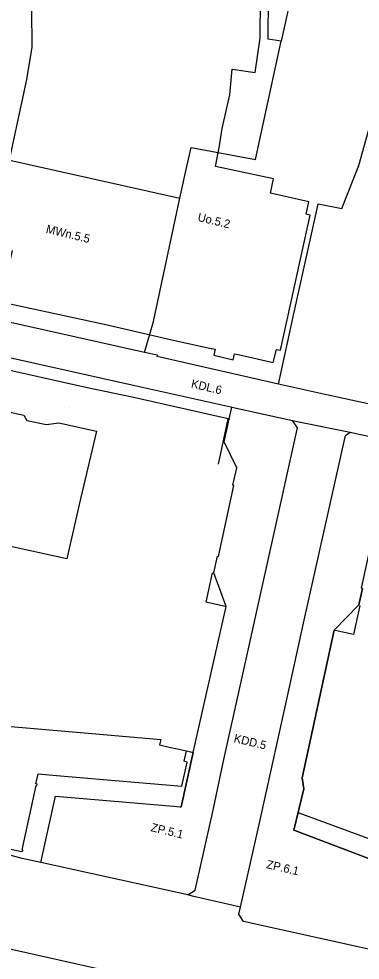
# Model space of a CAD drawing. Extents: x 7429686 to 7432896, y 5547954 to 5550600.
# Drawn here: x 7431167.9 to 7431331.5, y 5549633.8 to 5550085.1 of the extents above; entities that cross this region are included whole.
import ezdxf

# ---------------------------------------------------------------- set-up
doc = ezdxf.new("R2010")
doc.units = 0
for name, color, linetype in [('linie rozgraniczające', 7, 'Continuous'), ('obowiązująca linia zabudowy', 7, 'Continuous'), ('oznaczenia przeznaczeń', 7, 'Continuous')]:
    doc.layers.add(name, color=color, linetype=linetype)

msp = doc.modelspace()

# ---------------------------------------------------------------- linework, layer by layer
at = {"layer": 'linie rozgraniczające'}
for p, q in [((7431332.59, 5549812.04), (7431330.89, 5549804.16)), ((7431330.89, 5549804.16), (7431319.02, 5549792.1)), ((7431319.02, 5549792.1), (7431303.72, 5549721.28)), ((7431303.72, 5549721.28), (7431304.47, 5549715.98)), ((7431300.13, 5549695.97), (7431359.15, 5549673.6))]:
    msp.add_line(p, q, dxfattribs=at)
for points in [[(7431302.5, 5550115.02), (7431293.68, 5550074.41)], [(7431287.45, 5550075.33), (7431287.61, 5550096.06)], [(7431281.37, 5550017.75), (7431293.68, 5550074.41)], [(7431293.68, 5550074.41), (7431287.45, 5550075.33)], [(7431330.83, 5550014.86), (7431336.35, 5550034.33)], [(7431248.36, 5550014.31), (7431250.5, 5550023.42)], [(7431250.5, 5550023.42), (7431281.37, 5550017.75)], [(7431157.75, 5550018.66), (7431245.1, 5549999.15)], [(7431245.1, 5549999.15), (7431248.36, 5550014.31)], [(7431322.65, 5549994.25), (7431330.83, 5550014.86)], [(7431232.38, 5549940.01), (7431245.1, 5549999.15)], [(7431310.03, 5549990.54), (7431311.41, 5549996.45)], [(7431311.41, 5549996.45), (7431322.65, 5549994.25)], [(7431299.92, 5549944.45), (7431310.03, 5549990.54)], [(7431228.11, 5549925.18), (7431145.92, 5549943.57)], [(7431292.38, 5549910.01), (7431299.92, 5549944.45)], [(7431228.11, 5549925.18), (7431232.38, 5549940.01)], [(7431143.92, 5549927.01), (7431223.5, 5549909.33)], [(7431234.37, 5549923.82), (7431228.11, 5549925.18)], [(7431234.24, 5549923.16), (7431234.37, 5549923.82)], [(7431292.36, 5549910.01), (7431234.24, 5549923.16)], [(7431292.38, 5549910.01), (7431292.36, 5549910.01)], [(7431313.84, 5549905.24), (7431292.38, 5549910.01)], [(7431223.5, 5549909.33), (7431269.5, 5549899.12)], [(7431342.73, 5549898.88), (7431313.84, 5549905.24)], [(7431141.55, 5549901.35), (7431170.32, 5549895.1)], [(7431266.37, 5549882.27), (7431269.99, 5549899.01)], [(7431269.5, 5549899.12), (7431269.99, 5549899.01)], [(7431269.99, 5549899.01), (7431299.12, 5549892.54)], [(7431170.32, 5549895.1), (7431171.78, 5549892.56)], [(7431171.78, 5549892.56), (7431181.24, 5549890.55)], [(7431181.24, 5549890.55), (7431187.09, 5549891.39)], [(7431187.09, 5549891.39), (7431205.08, 5549887.43)], [(7431299.12, 5549892.54), (7431302.05, 5549891.89)], [(7431301.4, 5549888.96), (7431299.12, 5549892.54)], [(7431302.05, 5549891.89), (7431326.76, 5549886.99)], [(7431205.08, 5549887.43), (7431196.9, 5549852.2)], [(7431274.01, 5549765.16), (7431301.4, 5549888.96)], [(7431324.41, 5549885.42), (7431326.76, 5549886.99)], [(7431326.76, 5549886.99), (7431355.15, 5549880.69)], [(7431304.38, 5549795.32), (7431324.41, 5549885.42)], [(7431272.31, 5549869.87), (7431266.37, 5549882.27)], [(7431270.47, 5549861.47), (7431272.31, 5549869.87)], [(7431263.52, 5549827.4), (7431270.91, 5549861.34)], [(7431270.91, 5549861.34), (7431270.47, 5549861.47)], [(7431350.69, 5549635.72), (7431359.15, 5549673.6), (7431300.13, 5549695.97), (7431299.66, 5549696.15), (7431304.47, 5549715.98), (7431303.72, 5549721.28), (7431319.02, 5549792.1), (7431330.89, 5549804.16), (7431332.59, 5549812.04), (7431332.2, 5549812.2), (7431339.7, 5549846.45), (7431340.14, 5549846.42), (7431341.93, 5549854.71), (7431345.63, 5549857.59), (7431346.28, 5549858.1)], [(7431196.9, 5549852.2), (7431190.87, 5549826.26)], [(7431190.87, 5549826.26), (7431164.77, 5549831.94)], [(7431261.3, 5549819.53), (7431263.05, 5549827.55)], [(7431263.05, 5549827.55), (7431263.52, 5549827.4)], [(7431267.24, 5549803.35), (7431261.3, 5549819.53)], [(7431251.53, 5549733.37), (7431267.24, 5549803.35)], [(7431297.92, 5549766.13), (7431304.38, 5549795.32)], [(7431266.23, 5549729.93), (7431274.01, 5549765.16)], [(7431283.38, 5549700.36), (7431297.92, 5549766.13)], [(7431160.38, 5549746.12), (7431212.2, 5549741.68)], [(7431212.2, 5549741.68), (7431235.9, 5549739.65)], [(7431235.9, 5549739.65), (7431235.3, 5549737.02)], [(7431235.3, 5549737.02), (7431240.02, 5549735.96)], [(7431240.02, 5549735.96), (7431243.97, 5549735.1)], [(7431243.97, 5549735.1), (7431248.21, 5549734.1)], [(7431248.21, 5549734.1), (7431251.53, 5549733.37)], [(7431245.68, 5549707.34), (7431251.53, 5549733.37)], [(7431251.53, 5549733.37), (7431251.53, 5549733.37), (7431245.68, 5549707.34)], [(7431251.53, 5549733.37), (7431251.53, 5549733.37)], [(7431260.67, 5549704.33), (7431266.23, 5549729.93)], [(7431304.47, 5549715.98), (7431299.66, 5549696.15), (7431300.13, 5549695.97)], [(7431178.47, 5549680.56), (7431185.5, 5549712.42)], [(7431185.5, 5549712.42), (7431242.08, 5549707.64)], [(7431242.08, 5549707.64), (7431245.18, 5549707.38)], [(7431245.18, 5549707.38), (7431245.68, 5549707.34)], [(7431252.43, 5549667.33), (7431260.67, 5549704.33)], [(7431274.14, 5549659.27), (7431283.38, 5549700.36)], [(7431169.5, 5549682.54), (7431144.11, 5549689.49)], [(7431178.47, 5549680.56), (7431169.5, 5549682.54)], [(7431248.85, 5549665.05), (7431178.47, 5549680.56)], [(7431248.85, 5549665.05), (7431252.43, 5549667.33)], [(7431251.78, 5549664.4), (7431248.85, 5549665.05)], [(7431274.14, 5549659.27), (7431251.78, 5549664.4)], [(7431273.37, 5549655.85), (7431274.14, 5549659.27)], [(7431275.64, 5549652.27), (7431273.37, 5549655.85)], [(7431350.69, 5549635.72), (7431275.64, 5549652.27)], [(7431154.15, 5549641.32), (7431217.12, 5549627.23)]]:
    msp.add_lwpolyline(points, dxfattribs=at)
at = {"layer": 'obowiązująca linia zabudowy'}
for p, q in [((7431260.62, 5549926.99), (7431261.98, 5549926.69)), ((7431261.98, 5549926.69), (7431261.33, 5549923.82)), ((7431261.33, 5549923.82), (7431270.69, 5549921.69)), ((7431270.69, 5549921.69), (7431271.34, 5549924.52)), ((7431271.34, 5549924.52), (7431273.03, 5549924.13)), ((7431192.06, 5549898.79), (7431192.06, 5549898.79))]:
    msp.add_line(p, q, dxfattribs=at)
for points in [[(7431281.13, 5550059.4), (7431283.49, 5550075.92), (7431283.69, 5550095.26), (7431280.35, 5550111.61), (7431270.28, 5550128.36), (7431259.85, 5550141.49), (7431247.46, 5550147.97), (7431237.1, 5550160.93), (7431224.11, 5550167.3), (7431213.73, 5550180.15), (7431226.04, 5550202.46), (7431238.24, 5550212.54), (7431222.69, 5550231.34)], [(7431150.34, 5550144.25), (7431155, 5550138.59), (7431165.07, 5550121.75), (7431172.7, 5550105.48), (7431174.01, 5550089.79), (7431174.15, 5550071.53), (7431171.53, 5550056.01), (7431161.22, 5550007.85)], [(7431262.1, 5550014.41), (7431264.05, 5550024.31), (7431265.42, 5550032.52), (7431269.09, 5550048.76), (7431270.2, 5550060.95), (7431281.13, 5550059.4)], [(7431273.03, 5549924.13), (7431289.82, 5549920.3), (7431291.34, 5549926.63), (7431293.32, 5549926.25), (7431307.56, 5549991.06), (7431305.6, 5549991.5), (7431306.93, 5549997.4), (7431288.48, 5550001.54), (7431290, 5550008.38), (7431262.1, 5550014.41)], [(7431164.73, 5549974.03), (7431159.32, 5549949.51), (7431209.59, 5549938.54)], [(7431209.59, 5549938.54), (7431209.59, 5549938.54)], [(7431209.59, 5549938.54), (7431243.33, 5549930.77), (7431260.12, 5549927.1), (7431260.62, 5549926.99)], [(7431260.62, 5549926.99), (7431260.62, 5549926.99)], [(7431273.03, 5549924.13), (7431273.03, 5549924.13)], [(7431201.53, 5549908.12), (7431154.23, 5549918.55), (7431152.93, 5549911.84), (7431152.72, 5549910.76), (7431152.14, 5549907.74)], [(7431263.56, 5549871.59), (7431268.26, 5549893.37), (7431222.15, 5549903.7), (7431201.53, 5549908.12)], [(7431192.06, 5549898.79), (7431192.06, 5549898.79)], [(7431266.72, 5549803.32), (7431257.71, 5549805.42), (7431260.78, 5549819.49)], [(7431331.35, 5549803.91), (7431328.33, 5549789.9), (7431319.48, 5549791.85)], [(7431176.96, 5549722.4), (7431177.11, 5549723.09), (7431186.02, 5549722.33), (7431246.01, 5549717.27), (7431246.08, 5549717.26), (7431248.58, 5549728.79), (7431247.07, 5549729.2), (7431248.21, 5549734.1), (7431251.04, 5549733.48)], [(7431144.34, 5549693.38), (7431155.14, 5549691.05), (7431158.35, 5549690.36), (7431157.96, 5549688.36), (7431169.25, 5549685.92), (7431169.32, 5549686.22), (7431169.79, 5549686.12), (7431169.91, 5549686.68), (7431169.53, 5549686.77), (7431176.28, 5549717.57), (7431176.56, 5549717.5), (7431176.72, 5549718.22), (7431176.06, 5549718.37), (7431176.96, 5549722.4)], [(7431302.17, 5549704.38), (7431366.43, 5549680.74)]]:
    msp.add_lwpolyline(points, dxfattribs=at)

# ---------------------------------------------------------------- texts
at = {"layer": 'oznaczenia przeznaczeń'}
for s, rotation, p in [('Uo.5.2', 346.4891, (7431253.32, 5549988.31)), ('MWn.5.5', 346.4891, (7431180.66, 5549982.61)), ('KDL.6', 346.4891, (7431250.21, 5549908.5)), ('KDD.5', 346.4891, (7431270.67, 5549738.42)), ('ZP.5.1', 346.4891, (7431230.9, 5549695.71)), ('ZP.6.1', 347.0609, (7431286.27, 5549677.99))]:
    msp.add_text(s, height=4, rotation=rotation, dxfattribs=at).set_placement(p)

doc.saveas('drawing.dxf')
